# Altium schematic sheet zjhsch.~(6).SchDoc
size A4
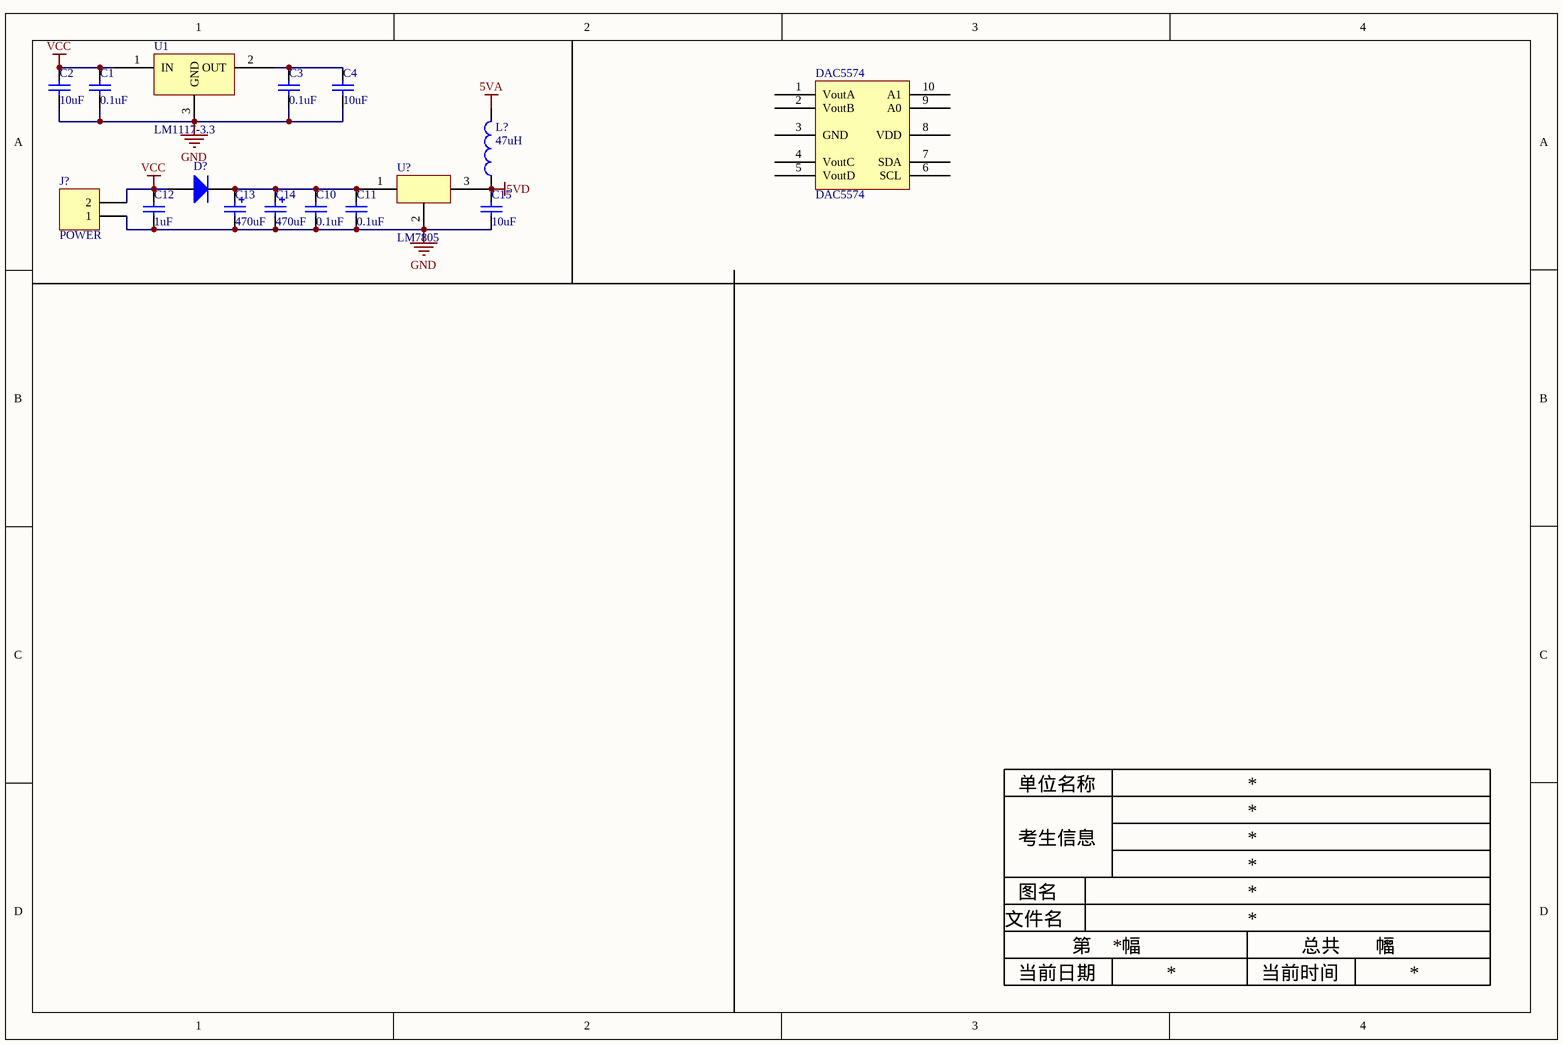
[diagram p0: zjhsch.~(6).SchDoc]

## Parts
C1  value 0.1uF  [RAD-0.3]  (hidden comment: Cap)
C2  value 10uF  [RAD-0.3]  (hidden comment: Cap)
C3  value 0.1uF  [RAD-0.3]  (hidden comment: Cap)
C4  value 10uF  [RAD-0.3]  (hidden comment: Cap)
C10  value 0.1uF  [RAD-0.3]  (hidden comment: Cap)
C11  value 0.1uF  [RAD-0.3]  (hidden comment: Cap)
C12  value 1uF  [RAD-0.3]  (hidden comment: Cap)
C13  value 470uF  [POLAR0.8]  (hidden comment: Cap Pol2)
C14  value 470uF  [POLAR0.8]  (hidden comment: Cap Pol2)
C15  value 10uF  [RAD-0.3]  (hidden comment: Cap)
D?  Diode  [SMC]  (value not drawn)
DAC5574  DAC5574
J?  POWER  [HDR1X2]
L?  47uH  [DIODE_SMC]
U1  LM1117-3.3  [LM1117-3.3]
U?  LM7805  [TO-220AB]

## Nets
5VA: L?.2
5VD: C15.2 L?.1 U?.3
GND: C1.1 C2.1 C3.1 C4.1 C10.1 C11.1 C12.1 C13.2 C14.2 C15.1 J?.1 U1.3(GND) U?.2
VCC: C1.2 C2.2 C12.2 D?.1(A) J?.2 U1.1(IN)
NetC3_2: C3.2 C4.2 U1.2(OUT)
NetC10_2: C10.2 C11.2 C13.1 C14.1 D?.2(K) U?.1

Not connected (* = marked no-connect by the designer): DAC5574 1(VoutA) 2(VoutB) 3(GND) 4(VoutC) 5(VoutD) 6(SCL) 7(SDA) 8(VDD) 9(A0) 10(A1)

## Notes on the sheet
- 单位名称
- 考生信息
- 文件名
- 图名
- 当前日期
- 第      幅
- 当前时间
- 总共       幅

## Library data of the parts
C1-C4 C10-C12 C15 = Cap: Capacitor
C13 C14 = Cap Pol2: Polarized Capacitor (Axial)
D? = Diode: Default Diode
J? = Header 2: Header, 2-Pin
L? = Inductor47uH
U? = 7805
